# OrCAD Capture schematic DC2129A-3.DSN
size Custom; title: 5V / 1.3 AMP AT VIN AS LOW AS 2.4V; rev: 3; note: DEMO CIRCUIT 2129A
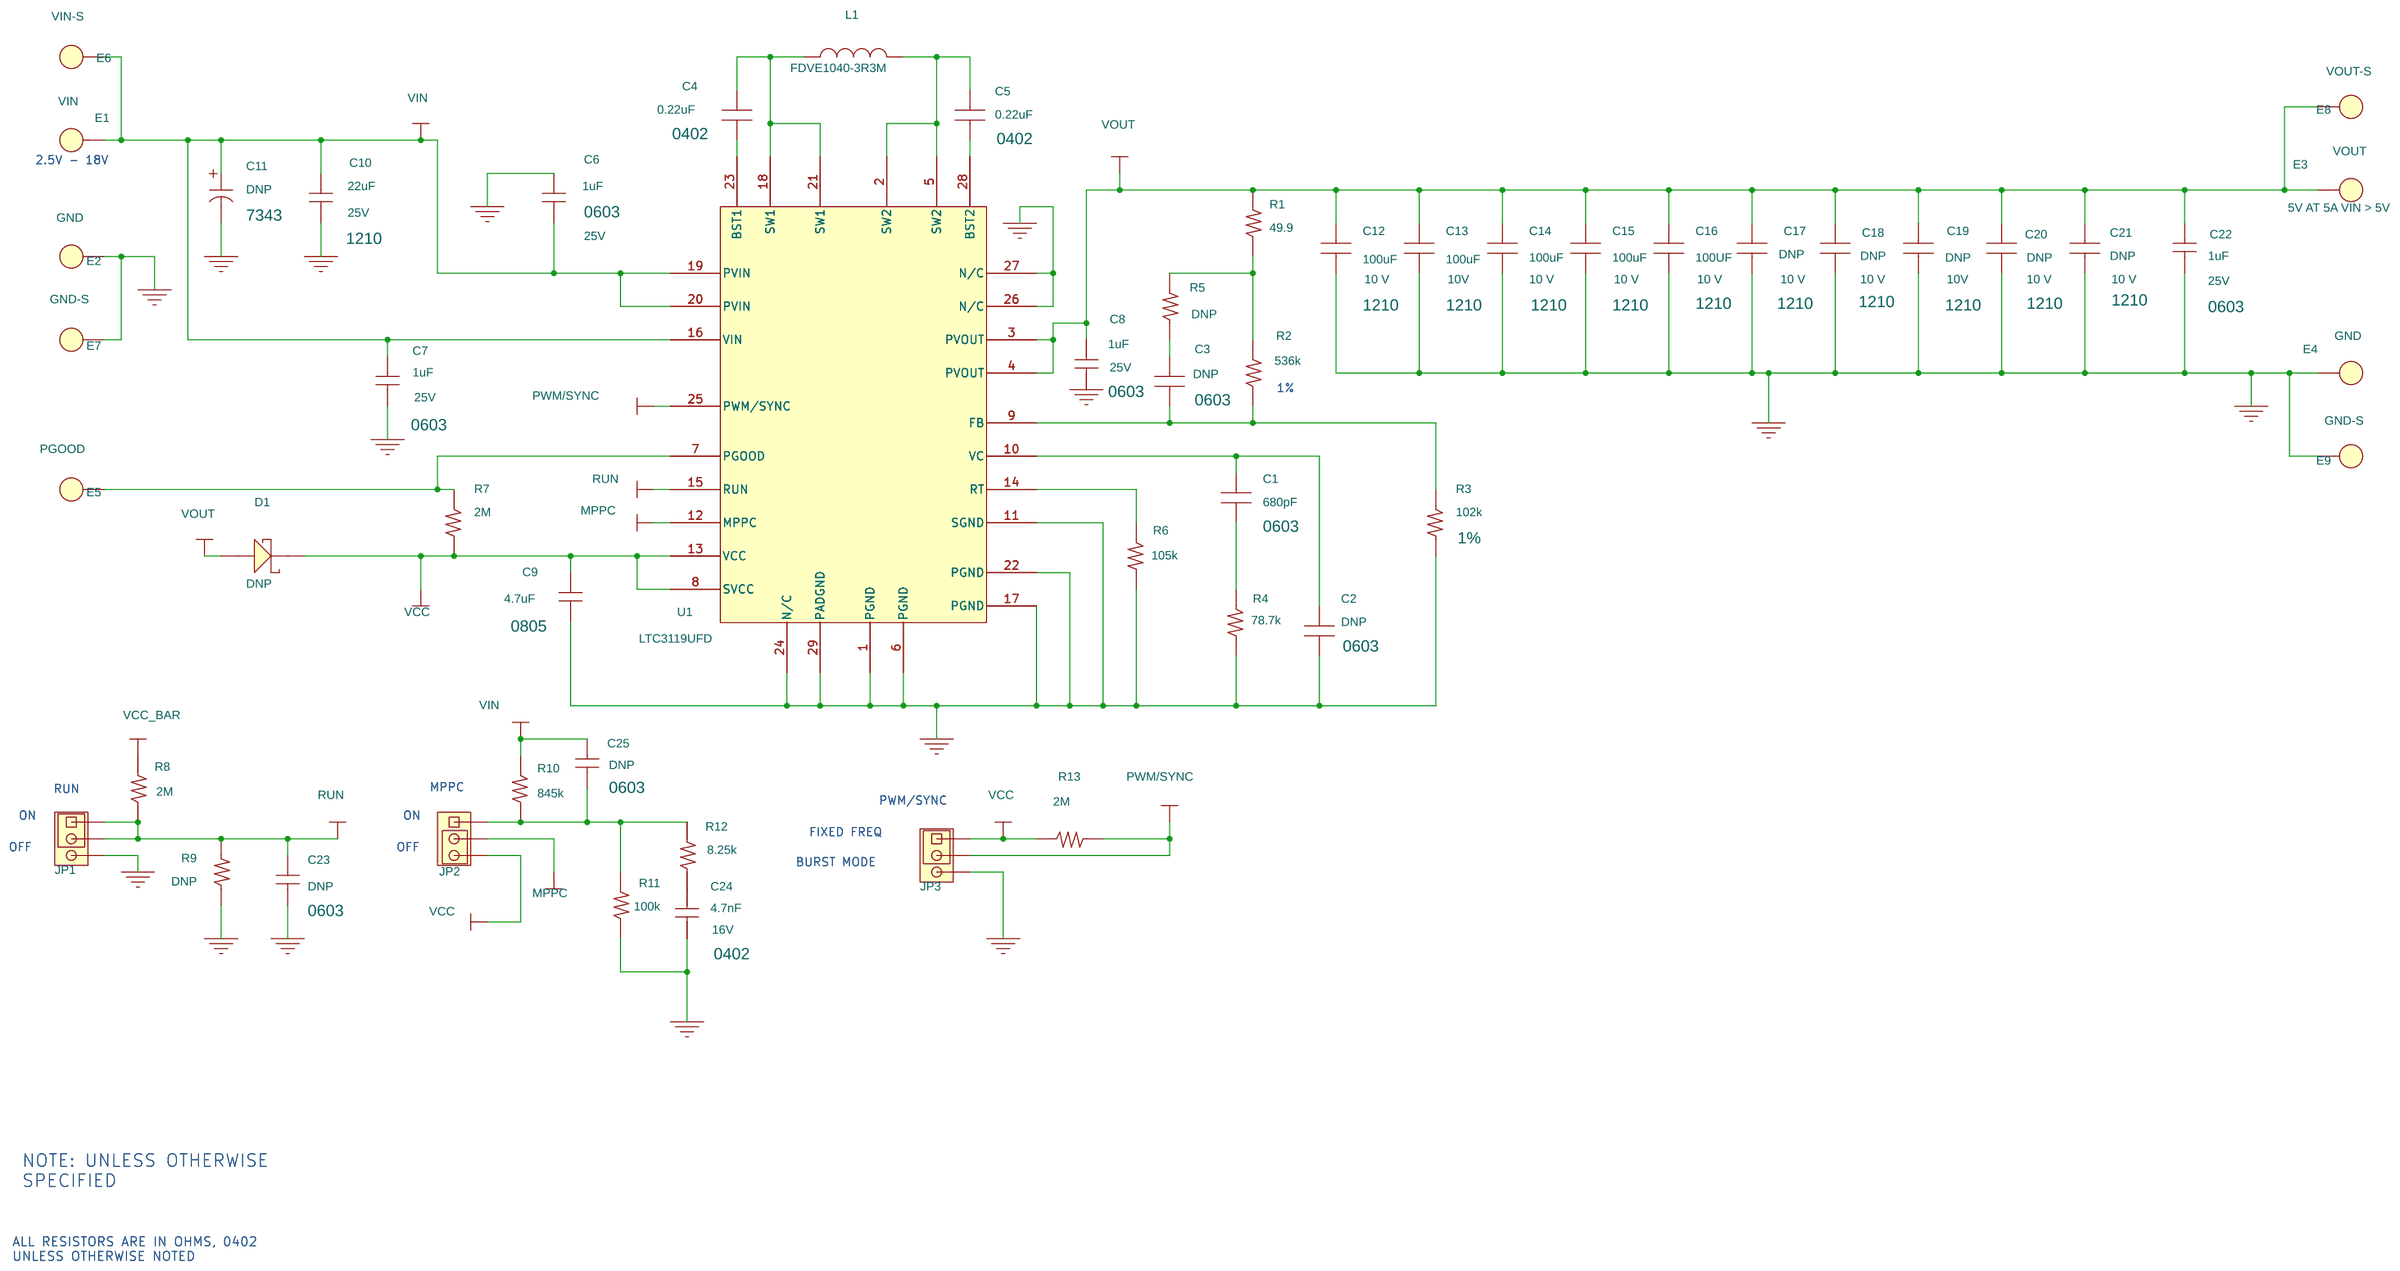
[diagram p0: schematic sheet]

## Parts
C1  680pF  [0603]
C2  DNP  [0603]
C3  DNP  [0603]
C4  0.22uF  [0402]
C5  0.22uF  [0402]
C6  1uF  [0603]
C7  1uF  [0603]
C8  1uF  [0603]
C9  4.7uF  [0805]
C10  22uF  [1210]
C11  DNP  [7343]
C12  100uF  [1210]
C13  100uF  [1210]
C14  100uF  [1210]
C15  100uF  [1210]
C16  100UF  [1210]
C17  DNP  [1210]
C18  DNP  [1210]
C19  DNP  [1210]
C20  DNP  [1210]
C21  DNP  [1210]
C22  1uF  [0603]
C23  DNP  [0603]
C24  4.7nF  [0402]
C25  DNP  [0603]
D1  DNP  [DFN1006-2]
E1  VIN  [KEY-575-4]
E2  GND  [KEY-575-4]
E3  VOUT  [KEY-575-4]
E4  GND  [KEY-575-4]
E5  PGOOD  [MILL-MAX-2501-2]
E6  VIN-S  [MILL-MAX-2501-2]
E7  GND-S  [MILL-MAX-2501-2]
E8  VOUT-S  [MILL-MAX-2501-2]
E9  GND-S  [MILL-MAX-2501-2]
JP1  HD1X3-079  [HD1X3-079]
JP2  HD1X3-079  [HD1X3-079]
JP3  HD1X3-079  [HD1X3-079]
L1  FDVE1040-3R3M  [IND-TOKO-FDVE1040]
R1  49.9  [0402-SMALL]
R2  536k  [0402-SMALL]
R3  102k  [0402-SMALL]
R4  78.7k  [0402-SMALL]
R5  DNP  [0402-SMALL]
R6  105k  [0402-SMALL]
R7  2M  [0402-SMALL]
R8  2M  [0402-SMALL]
R9  DNP  [0402-SMALL]
R10  845k  [0402-SMALL]
R11  100k  [0402-SMALL]
R12  8.25k  [0402-SMALL]
R13  2M  [0402-SMALL]
U1  LTC3119UFD  [LTC-UFD-28-1712]

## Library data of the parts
C1-C3 = CAPACITOR
C4 = Capacitor_0805
C5 = Capacitor_0805_1
C6-C8 C10 C22 = CAP-NP: VOLT: 25V
C9 C23 C25 = CAP-NP
C11 = CAP
C12 = Capacitor_1812_5: Voltage Rating: 10 V
C13 = Capacitor_1812: Voltage Rating: 10V
C14 = Capacitor_1812_8: Voltage Rating: 10 V
C15 = Capacitor_1812_9: Voltage Rating: 10 V
C16 = Capacitor_1812_2: Voltage Rating: 10 V
C17 = Capacitor_1812_7: Voltage Rating: 10 V
C18 = Capacitor_1812_3: Voltage Rating: 10 V
C19 = Capacitor_1812_6: Voltage Rating: 10V
C20 = Capacitor_1812_4: Voltage Rating: 10 V
C21 = Capacitor_1812_1: Voltage Rating: 10 V
C24 = CAP-NP: VOLT: 16V
D1 = DIODE_SCHOTTKY_1
E1 = E: v: 2.2V - 15V
E2 E4-E9 = E: v: 5V@ 2A
E3 = E: v: 5V AT 5A VIN > 5V
JP1 JP3 = HD1X3_15
JP2 = HD1X3_14
L1 = inductor-EPLxxx
R1 R2 R4-R13 = R
R3 = R: tolerance: 1%
U1 = LTC3119UFD

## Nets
GND: C2.2 C6.1 C7.2 C8.2 C9.2 C10.2 C11.2 C12.2 C13.2 C14.2 C15.2 C16.2 C17.2 C18.2 C19.2 C20.2 C21.2 C22.2 C23.2 C24.2 E2.1(A) E4.1(A) E7.1(A) E9.1(A) JP1.3 JP3.3 R3.2 R4.2 R6.2 R9.1 R11.1 U1.1(PGND) U1.6(PGND) U1.11(SGND) U1.17(PGND) U1.22(PGND) U1.24(N/C) U1.26(N/C) U1.27(N/C) U1.29(PADGND)
VCC: C9.1 D1.1(C) JP2.3 JP3.1 R7.2 R13.1 U1.8(SVCC) U1.13(VCC)
VIN: C6.2 C7.1 C10.1 C11.1 C25.1 E1.1(A) E6.1(A) R8.2 R10.1 U1.16(VIN) U1.19(PVIN) U1.20(PVIN)
MPPC: JP2.2 U1.12(MPPC)
PWM/SYNC: JP3.2 R13.2 U1.25(PWM/SYNC)
RUN: C23.1 JP1.1 JP1.2 R8.1 R9.2 U1.15(RUN)
VOUT: C8.1 C12.1 C13.1 C14.1 C15.1 C16.1 C17.1 C18.1 C19.1 C20.1 C21.1 C22.1 D1.2(A) E3.1(A) E8.1(A) R1.2 U1.3(PVOUT) U1.4(PVOUT)
N17135012: C25.2 JP2.1 R10.2 R11.2 R12.2
N17149866: C3.2 R2.1 R3.1 U1.9(FB)
N17407194: C1.2 R4.1
N17437975: C1.1 C2.1 U1.10(VC)
N17454561: C3.1 R5.1
N17454988: R1.1 R2.2 R5.2
N17457761: R6.1 U1.14(RT)
N17459622: C4.2 L1.1 U1.18(SW1) U1.21(SW1)
N17474741: E5.1(A) R7.1 U1.7(PGOOD)
N17519682: C4.1 U1.23(BST1)
N17519716: C5.2 U1.28(BST2)
N17519719: C5.1 L1.2 U1.2(SW2) U1.5(SW2)
N17561800: C24.1 R12.1

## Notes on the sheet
- 2.5V - 18V
- 1%
- RUN
- MPPC
- PWM/SYNC
- ON
- ON
- FIXED FREQ
- OFF
- OFF
- BURST MODE
- NOTE: UNLESS OTHERWISE
  SPECIFIED
- ALL RESISTORS ARE IN OHMS, 0402
   UNLESS OTHERWISE NOTED
